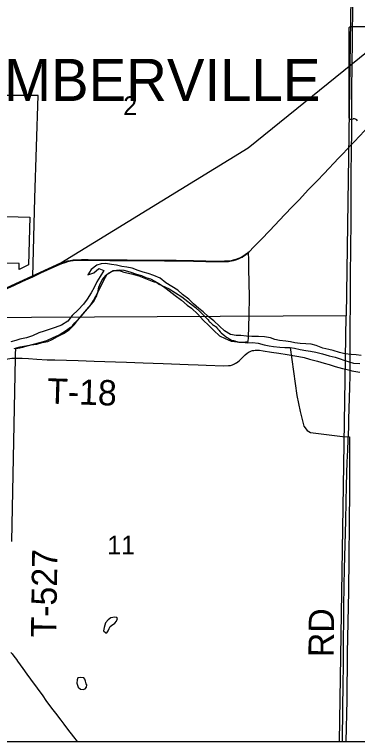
# Model space of a CAD drawing. Extents: x 0 to 34, y 0 to 22.
# Drawn here: x 5.678 to 6.448, y 14.1 to 15.733 of the extents above; entities that cross this region are included whole.
import ezdxf

# ---------------------------------------------------------------- set-up
doc = ezdxf.new("R2010")
doc.units = 0
for name, color, linetype in [('GM_X_City_Street', 7, 'Continuous'), ('GM_X_Corporation_Text', 7, 'Continuous'), ('GM_X_Major_River', 7, 'Continuous'), ('GM_X_Minor_Lake', 7, 'Continuous'), ('GM_X_Minor_River', 7, 'Continuous'), ('GM_X_Rail_Line', 7, 'Continuous'), ('GM_X_Section', 7, 'Continuous'), ('GM_X_Section_Text', 7, 'Continuous'), ('GM_X_State_Route', 7, 'Continuous'), ('GM_X_State_Shield', 7, 'Continuous'), ('GM_X_Township_Road', 7, 'Continuous'), ('GM_X_Township_Road_Text', 7, 'Continuous'), ('GM_X_US_Route', 7, 'Continuous'), ('SH_Cut_Line', 7, 'Continuous'), ('SH_Data', 7, 'Continuous')]:
    doc.layers.add(name, color=color, linetype=linetype)

msp = doc.modelspace()

# ---------------------------------------------------------------- linework, layer by layer
at = {"layer": 'GM_X_City_Street'}
msp.add_lwpolyline([(5.415, 14.1), (6.4082, 14.1), (6.4232, 15.0563), (5.4321, 15.051)], close=True, dxfattribs=at)
at = {"layer": 'GM_X_Major_River'}
for points in [[(6.457, 14.9672), (6.4456, 14.9683), (6.4347, 14.9689), (6.4199, 14.9704), (6.4079, 14.9737), (6.394, 14.9779), (6.3838, 14.9808), (6.371, 14.9837), (6.3557, 14.9894), (6.3444, 14.9924), (6.3327, 14.9934), (6.3194, 14.9941), (6.3077, 14.9955), (6.2979, 14.9977), (6.2874, 14.9991), (6.273, 15.0005), (6.2628, 15.0031), (6.2531, 15.0063), (6.2399, 15.0089), (6.2263, 15.01), (6.2111, 15.0093), (6.199, 15.0107), (6.1866, 15.0117), (6.176, 15.012), (6.1635, 15.0142), (6.1501, 15.0221), (6.1382, 15.0327), (6.1256, 15.0447), (6.1134, 15.0545), (6.1015, 15.0647), (6.0919, 15.0725), (6.0804, 15.083), (6.0693, 15.0932), (6.0555, 15.1041), (6.0448, 15.1135), (6.0318, 15.1221), (6.0183, 15.1304), (6.0049, 15.1403), (5.9912, 15.1463), (5.9783, 15.1508), (5.9674, 15.1541), (5.9561, 15.1578), (5.9423, 15.163), (5.9302, 15.1652), (5.9193, 15.167), (5.9068, 15.1696), (5.8959, 15.1717), (5.8823, 15.1736), (5.8728, 15.1731), (5.8629, 15.1695), (5.8506, 15.1603), (5.8427, 15.148), (5.856, 15.1526), (5.8673, 15.1622), (5.8785, 15.1581), (5.8702, 15.1443), (5.8627, 15.1323), (5.8567, 15.1199), (5.8504, 15.1076), (5.8416, 15.0934), (5.8331, 15.0826), (5.8214, 15.0696), (5.8078, 15.057), (5.7977, 15.044), (5.7838, 15.0352), (5.7697, 15.0302), (5.7559, 15.0256), (5.7449, 15.0217), (5.7327, 15.0178), (5.7181, 15.011)], [(5.6769, 14.9824), (5.691, 14.9866), (5.7031, 14.9886), (5.7157, 14.9909), (5.7279, 14.9925), (5.7404, 14.996), (5.7526, 14.9987), (5.7626, 15.0031), (5.7749, 15.01), (5.7879, 15.0161), (5.801, 15.0249), (5.8123, 15.0361), (5.8197, 15.0457), (5.8302, 15.0576), (5.8376, 15.0663), (5.8482, 15.0783), (5.8556, 15.0904), (5.8608, 15.1005), (5.8676, 15.1132), (5.8787, 15.1365), (5.8859, 15.1496), (5.8997, 15.158), (5.9138, 15.1592), (5.9236, 15.1586), (5.9371, 15.1552), (5.9522, 15.1495), (5.9631, 15.1466), (5.9732, 15.1425), (5.9833, 15.1389), (5.9934, 15.1341), (6.0039, 15.1278), (6.0158, 15.1199), (6.0254, 15.1121), (6.0392, 15.1019), (6.0529, 15.0909), (6.0656, 15.0803), (6.076, 15.0733), (6.0897, 15.06), (6.1022, 15.0461), (6.1148, 15.0347), (6.1259, 15.0231), (6.1388, 15.011), (6.1515, 15.005), (6.165, 14.9994), (6.179, 14.9979), (6.19, 14.9969), (6.2013, 14.9955), (6.2127, 14.9959), (6.2251, 14.9949), (6.2391, 14.9911), (6.2504, 14.9889), (6.2602, 14.9872), (6.2738, 14.9857), (6.2851, 14.9851), (6.2972, 14.9848), (6.307, 14.9834), (6.3195, 14.9808), (6.3328, 14.9785), (6.3432, 14.9764), (6.3549, 14.9743), (6.37, 14.9705), (6.3846, 14.9663), (6.3986, 14.9633), (6.4074, 14.9599), (6.42, 14.9556), (6.4301, 14.9527), (6.4399, 14.9498), (6.4535, 14.9487)], [(5.7181, 15.011), (5.7047, 15.0064), (5.6903, 15.0037), (5.6807, 15.0009), (5.67, 14.9977)]]:
    msp.add_lwpolyline(points, dxfattribs=at)
at = {"layer": 'GM_X_Minor_Lake'}
for p, q in [((5.8928, 14.3585), (5.8958, 14.3603)), ((5.8392, 14.2296), (5.8375, 14.2354))]:
    msp.add_line(p, q, dxfattribs=at)
for points in [[(5.8958, 14.3603), (5.9032, 14.3655), (5.9075, 14.3703), (5.9091, 14.376), (5.908, 14.3786), (5.9035, 14.3791), (5.8944, 14.3778), (5.8886, 14.3734), (5.8827, 14.3664), (5.8795, 14.3562), (5.8781, 14.3482), (5.883, 14.3443), (5.8856, 14.3443), (5.8884, 14.3488), (5.8908, 14.3536), (5.8928, 14.3585)], [(5.8375, 14.2354), (5.8361, 14.2396), (5.8339, 14.2427), (5.8271, 14.2436), (5.8206, 14.2426), (5.8186, 14.2381), (5.8177, 14.2309), (5.8212, 14.2217), (5.826, 14.2174), (5.8325, 14.2169), (5.837, 14.2183), (5.8398, 14.222), (5.8403, 14.2273), (5.8392, 14.2296)]]:
    msp.add_lwpolyline(points, dxfattribs=at)
at = {"layer": 'GM_X_Minor_River'}
msp.add_lwpolyline([(6.2972, 14.9848), (6.312, 14.877), (6.3198, 14.8408), (6.3281, 14.8083), (6.3354, 14.7986), (6.3429, 14.7943), (6.4146, 14.785), (6.4305, 14.7842), (6.4306, 14.6654), (6.4283, 14.4377), (6.4256, 14.2981), (6.4249, 14.1927), (6.4226, 14.1)], dxfattribs=at)
at = {"layer": 'GM_X_Rail_Line'}
msp.add_lwpolyline([(5.4683, 15.0207), (5.6332, 15.1067), (5.7819, 15.1753), (6.2027, 15.4338), (6.5076, 15.6796), (6.6489, 15.6828), (6.8134, 15.745), (7.4742, 16.0534)], dxfattribs=at)
at = {"layer": 'GM_X_Section'}
msp.add_lwpolyline([(5.476, 16.0344), (6.437, 16.0283), (6.4232, 15.0563), (5.4321, 15.051), (5.457, 16.0346)], close=True, dxfattribs=at)
at = {"layer": 'GM_X_State_Route'}
for points in [[(6.2043, 15.1994), (6.2161, 15.2115), (6.232, 15.2277), (6.2514, 15.2479), (6.2845, 15.283), (6.3029, 15.3019), (6.3181, 15.3175), (6.3381, 15.3392), (6.3576, 15.3593), (6.3739, 15.376), (6.4058, 15.41), (6.4156, 15.42), (6.4354, 15.441), (6.4419, 15.4479), (6.4756, 15.4837)], [(5.8491, 15.1812), (5.8922, 15.1807), (5.931, 15.1803), (5.9558, 15.1802), (6.0148, 15.1798), (6.0412, 15.1797), (6.063, 15.1794), (6.0801, 15.1791), (6.108, 15.1782), (6.1359, 15.1779), (6.1499, 15.1779), (6.1591, 15.1784), (6.1652, 15.1793), (6.1697, 15.1803), (6.1756, 15.1819), (6.1813, 15.1841), (6.1855, 15.186), (6.1896, 15.1881), (6.1935, 15.1905), (6.1972, 15.1932), (6.2013, 15.1965), (6.2043, 15.1994)], [(5.7193, 15.1438), (5.7373, 15.1526), (5.767, 15.1661), (5.7842, 15.1735), (5.7915, 15.1762), (5.7975, 15.178), (5.8036, 15.1793), (5.8098, 15.1802), (5.8176, 15.1809), (5.8285, 15.1813), (5.8441, 15.1813), (5.8491, 15.1812)], [(5.6934, 15.1321), (5.7034, 15.1367), (5.7193, 15.1438)], [(5.5151, 15.0465), (5.5212, 15.0496), (5.5602, 15.0689), (5.5853, 15.0812), (5.6106, 15.0931), (5.6302, 15.1025), (5.6498, 15.112), (5.678, 15.1249), (5.6934, 15.1321)]]:
    msp.add_lwpolyline(points, dxfattribs=at)
at = {"layer": 'GM_X_State_Shield'}
for p, q in [((6.4289, 15.7017), (6.4289, 15.5016)), ((6.5286, 15.7052), (6.4321, 15.7052))]:
    msp.add_line(p, q, dxfattribs=at)
for centre, major_axis, start_param, end_param in [((6.4326, 15.7021), (0.00382, 0), 1.712693, 3.28349), ((6.4327, 15.5012), (0.00385, 0), 3.00124, 4.508301), ((6.4333, 15.5216), (0.0294, 0), 4.665946, 4.897461), ((6.4393, 15.4901), (0.0106, 0), 0.519207, 1.627899)]:
    msp.add_ellipse(centre, major_axis=major_axis, ratio=0.8, start_param=start_param, end_param=end_param, dxfattribs=at)
at = {"layer": 'GM_X_Township_Road'}
for points in [[(6.4354, 15.441), (6.4358, 15.4549), (6.4358, 15.4766), (6.4358, 15.5093), (6.4361, 15.5637), (6.4367, 15.6196), (6.4373, 15.6725), (6.4382, 15.7595), (6.439, 15.8325), (6.4401, 15.918), (6.4406, 15.9444), (6.441, 15.9693), (6.4415, 15.9942), (6.4423, 16.0128), (6.4425, 16.0181)], [(5.6721, 14.5494), (5.6805, 14.9616), (5.6803, 14.9703), (5.6808, 14.9827), (5.6855, 14.9836), (5.69, 14.9841), (5.6969, 14.9859), (5.7062, 14.9888), (5.7351, 14.9961), (5.751, 15.0009), (5.765, 15.0073), (5.7785, 15.0137), (5.7973, 15.0256), (5.8013, 15.0289), (5.8042, 15.0308), (5.8081, 15.0339), (5.8098, 15.0355), (5.8136, 15.0405), (5.8166, 15.0432), (5.8177, 15.044), (5.8184, 15.0449), (5.8192, 15.0466), (5.8202, 15.0466), (5.8261, 15.0539), (5.8547, 15.0865), (5.8562, 15.0887), (5.8568, 15.0891), (5.8568, 15.0896), (5.8586, 15.0926), (5.8615, 15.0986), (5.8626, 15.1012), (5.8639, 15.1046), (5.865, 15.1087), (5.8677, 15.1204), (5.8695, 15.1257), (5.8752, 15.1368), (5.8836, 15.1473), (5.8894, 15.1522), (5.8974, 15.1561), (5.9045, 15.1577), (5.9075, 15.1579), (5.9129, 15.1576), (5.9179, 15.1566), (5.9239, 15.1544), (5.9408, 15.1506), (5.9574, 15.1457), (5.987, 15.134), (5.9921, 15.1322), (5.9946, 15.1323), (5.9965, 15.1315), (5.9983, 15.1299), (6.0006, 15.1279), (6.0252, 15.1164), (6.0541, 15.099), (6.0843, 15.0751), (6.0952, 15.0654), (6.1123, 15.0481), (6.1128, 15.0477), (6.1135, 15.0471), (6.1135, 15.0457), (6.1141, 15.0454), (6.1144, 15.0448), (6.1148, 15.0441), (6.1152, 15.0434), (6.1157, 15.0429), (6.1159, 15.0428), (6.1177, 15.0415), (6.1194, 15.0402), (6.1198, 15.0397), (6.1209, 15.0387), (6.1219, 15.0374), (6.123, 15.0364), (6.1252, 15.0349), (6.1263, 15.0342), (6.1307, 15.0315), (6.1329, 15.029), (6.1335, 15.0281), (6.1344, 15.0274), (6.1349, 15.0268), (6.1351, 15.0263), (6.1355, 15.0256), (6.1361, 15.0248), (6.1368, 15.0241), (6.1399, 15.0202), (6.1424, 15.0178), (6.1508, 15.0113), (6.1511, 15.0108), (6.1523, 15.0098), (6.1554, 15.0074), (6.157, 15.0065), (6.1616, 15.0035), (6.163, 15.0028), (6.1655, 15.0016), (6.1661, 15.0014), (6.1702, 15.0004), (6.1722, 14.9999), (6.1732, 14.9996), (6.1742, 14.9992), (6.1762, 14.9986), (6.1773, 14.9982), (6.1775, 14.9981), (6.1781, 14.9979), (6.1784, 14.9979), (6.1801, 14.9975), (6.1822, 14.9972), (6.1845, 14.997), (6.1859, 14.9968), (6.1872, 14.9967), (6.1891, 14.9968), (6.1907, 14.9969), (6.1914, 14.997), (6.1921, 14.997), (6.1963, 14.9971), (6.198, 14.9973), (6.2002, 14.9977), (6.2032, 14.9981), (6.2037, 15.0073), (6.205, 15.0571), (6.2062, 15.0985), (6.2045, 15.1623), (6.2041, 15.1801), (6.204, 15.1999), (6.2011, 15.1971), (6.197, 15.1938), (6.1932, 15.1911), (6.1893, 15.1887), (6.1853, 15.1865), (6.1811, 15.1846), (6.1753, 15.1825), (6.1694, 15.1808), (6.1649, 15.1799), (6.1589, 15.179), (6.1496, 15.1785), (6.1357, 15.1784), (6.1078, 15.1788), (6.0798, 15.1796), (6.0627, 15.1799), (6.041, 15.1803), (6.0146, 15.1803), (5.9556, 15.1807), (5.9308, 15.1808), (5.892, 15.1812), (5.8438, 15.1818), (5.8283, 15.1818), (5.8174, 15.1814), (5.8096, 15.1808), (5.8034, 15.1799), (5.7973, 15.1785), (5.7912, 15.1768), (5.7839, 15.174), (5.7668, 15.1666), (5.7371, 15.1531), (5.7191, 15.1444), (5.7234, 15.3202), (5.7311, 15.551), (5.6413, 15.5508)], [(6.432, 14.9337), (6.4322, 14.956), (6.4323, 14.9855), (6.4322, 15.0135), (6.4327, 15.1021), (6.4332, 15.1534), (6.4339, 15.2015), (6.4344, 15.2746), (6.4344, 15.3088), (6.4343, 15.3476), (6.4343, 15.3834), (6.4349, 15.4176), (6.4353, 15.4378), (6.4354, 15.441)], [(5.633, 15.28), (5.7126, 15.2774), (5.7096, 15.1706), (5.6884, 15.16), (5.6888, 15.1736), (5.4378, 15.1778)], [(5.6807, 14.9611), (5.6951, 14.9607), (5.7094, 14.9599), (5.728, 14.9588), (5.7516, 14.9576), (5.7684, 14.9571), (5.8212, 14.9555), (5.8573, 14.9543), (5.9051, 14.953), (5.9294, 14.9521), (5.9673, 14.9508), (6.012, 14.9491), (6.0679, 14.9468), (6.0909, 14.9459), (6.1089, 14.9453), (6.1485, 14.9439), (6.1586, 14.9442), (6.1612, 14.9443), (6.1632, 14.9447), (6.1654, 14.9453), (6.1679, 14.9462), (6.1704, 14.9473), (6.1725, 14.9484), (6.1746, 14.9496), (6.1765, 14.9508), (6.1796, 14.9529), (6.1831, 14.9557), (6.1962, 14.9681), (6.201, 14.9719), (6.2031, 14.9736), (6.2053, 14.975), (6.2075, 14.976), (6.2103, 14.9771), (6.213, 14.9779), (6.2158, 14.9784), (6.2188, 14.9788), (6.2221, 14.9789), (6.2249, 14.9788), (6.2281, 14.9786), (6.2367, 14.9776), (6.2557, 14.9746), (6.2719, 14.9719), (6.2902, 14.9694), (6.308, 14.9664), (6.3171, 14.9646), (6.3287, 14.9621), (6.341, 14.9589), (6.3588, 14.9539), (6.3736, 14.9498), (6.3847, 14.9464), (6.3981, 14.9424), (6.4145, 14.9377), (6.4224, 14.9359), (6.4284, 14.9345), (6.432, 14.9337)], [(5.4346, 14.9329), (5.437, 14.9328), (5.4432, 14.9326), (5.4527, 14.934), (5.4695, 14.9361), (5.4756, 14.937), (5.4878, 14.9391), (5.5062, 14.9421), (5.5185, 14.9438), (5.5369, 14.9461), (5.5477, 14.9474), (5.5616, 14.9487), (5.571, 14.9494), (5.5806, 14.9505), (5.5911, 14.9508), (5.605, 14.9512), (5.6111, 14.9513), (5.6185, 14.9514), (5.6249, 14.9521), (5.6317, 14.9531), (5.6523, 14.9577), (5.663, 14.9594), (5.6723, 14.9606), (5.6807, 14.9611)], [(6.4149, 14.1), (6.415, 14.1061), (6.4165, 14.2335), (6.4168, 14.2661), (6.4173, 14.3112), (6.4174, 14.3314), (6.4178, 14.3687), (6.4182, 14.4029), (6.4188, 14.4495), (6.4194, 14.4884), (6.422, 14.5956), (6.4229, 14.6391), (6.4235, 14.6733), (6.4245, 14.7028), (6.4257, 14.7277), (6.4268, 14.7541), (6.4277, 14.7774), (6.4288, 14.8053), (6.4294, 14.8239), (6.4312, 14.8954), (6.4319, 14.9218), (6.432, 14.9337)], [(6.432, 14.9337), (6.4361, 14.9328), (6.4451, 14.9313), (6.4539, 14.9298)], [(5.6696, 14.3002), (5.6729, 14.2968), (5.6767, 14.2916), (5.6823, 14.2841), (5.6849, 14.2803), (5.6968, 14.2639), (5.7058, 14.2512), (5.7139, 14.2399), (5.7287, 14.2199), (5.7415, 14.2023), (5.7487, 14.1922), (5.7614, 14.1745), (5.7698, 14.1634), (5.7823, 14.1475), (5.7889, 14.1389), (5.7973, 14.1277), (5.8105, 14.1105), (5.8185, 14.1)]]:
    msp.add_lwpolyline(points, dxfattribs=at)
at = {"layer": 'GM_X_US_Route'}
msp.add_lwpolyline([(3.4084, 14.1), (7.4244, 14.1)], dxfattribs=at)
at = {"layer": 'SH_Cut_Line'}
msp.add_lwpolyline([(2.1, 20.9), (2.1, 14.1), (7.4244, 14.1)], dxfattribs=at)
at = {"layer": 'SH_Data'}
msp.add_line((2.1, 14.1), (8.9, 14.1), dxfattribs=at)

# ---------------------------------------------------------------- texts
at = {"layer": 'GM_X_Corporation_Text'}
msp.add_text('PEMBERVILLE', height=0.094697, rotation=0, dxfattribs=at).set_placement((5.4856, 15.5386))
at = {"layer": 'GM_X_Section_Text'}
for s, height, p in [('2', 0.0419, (5.9223, 15.5072)), ('11', 0.04186, (5.8864, 14.5202))]:
    msp.add_text(s, height=height, rotation=0, dxfattribs=at).set_placement(p)
at = {"layer": 'GM_X_Township_Road_Text'}
for s, rotation, p in [('T-18', 358.2329, (5.7508, 14.8591)), ('T-527', 89.1569, (5.7717, 14.3333)), ('RD', 89.5097, (6.3951, 14.2892))]:
    msp.add_text(s, height=0.05682, rotation=rotation, dxfattribs=at).set_placement(p)

doc.saveas('drawing.dxf')
